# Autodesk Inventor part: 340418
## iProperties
Shininess: 80.0
Length Units: 11269
Angle Units: 11279
Time Units: 11290
Mass Units: 11284
Length Display Precision: 3
Angle Display Precision: 2
Compacted: True
Company: Pneumax S.p.A.
Part Number: 340418
Material: Default
Description: ASTA TRIPLA+ANELLO GIREVOLE Ø4 G1/8"
Document SubType Name: Modellazione
Catalog Web Link: www.pneumaxspa.com
Density: 1.59
Volumn: 0.8648857994912436
Area: 17.092995283760587
PropertySet Name: Model Information
Control State: 0
Master: False
Checked Out: False
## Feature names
1. Smusso11 [Chamfer]
2. Revolution6
3. Rivoluzione7 [Revolution]
4. Estrusione12 [Extrusion]
5. Smusso10 [Chamfer]
6. Foro7 [Hole]
7. Estrusione11 [Extrusion]
8. Foro6 [Hole]
9. Serie rettangolare1 [Rectangular Pattern]
10. Serie rettangolare2 [Rectangular Pattern]
11. Foro8 [Hole]
